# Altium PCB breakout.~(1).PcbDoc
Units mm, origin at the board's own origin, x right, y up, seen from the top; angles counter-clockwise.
Board outline 43.1 x 56.5 mm, 2 copper layers (Top Layer, Bottom Layer); 2 components, 0 nets, 95 pads, 39 vias.
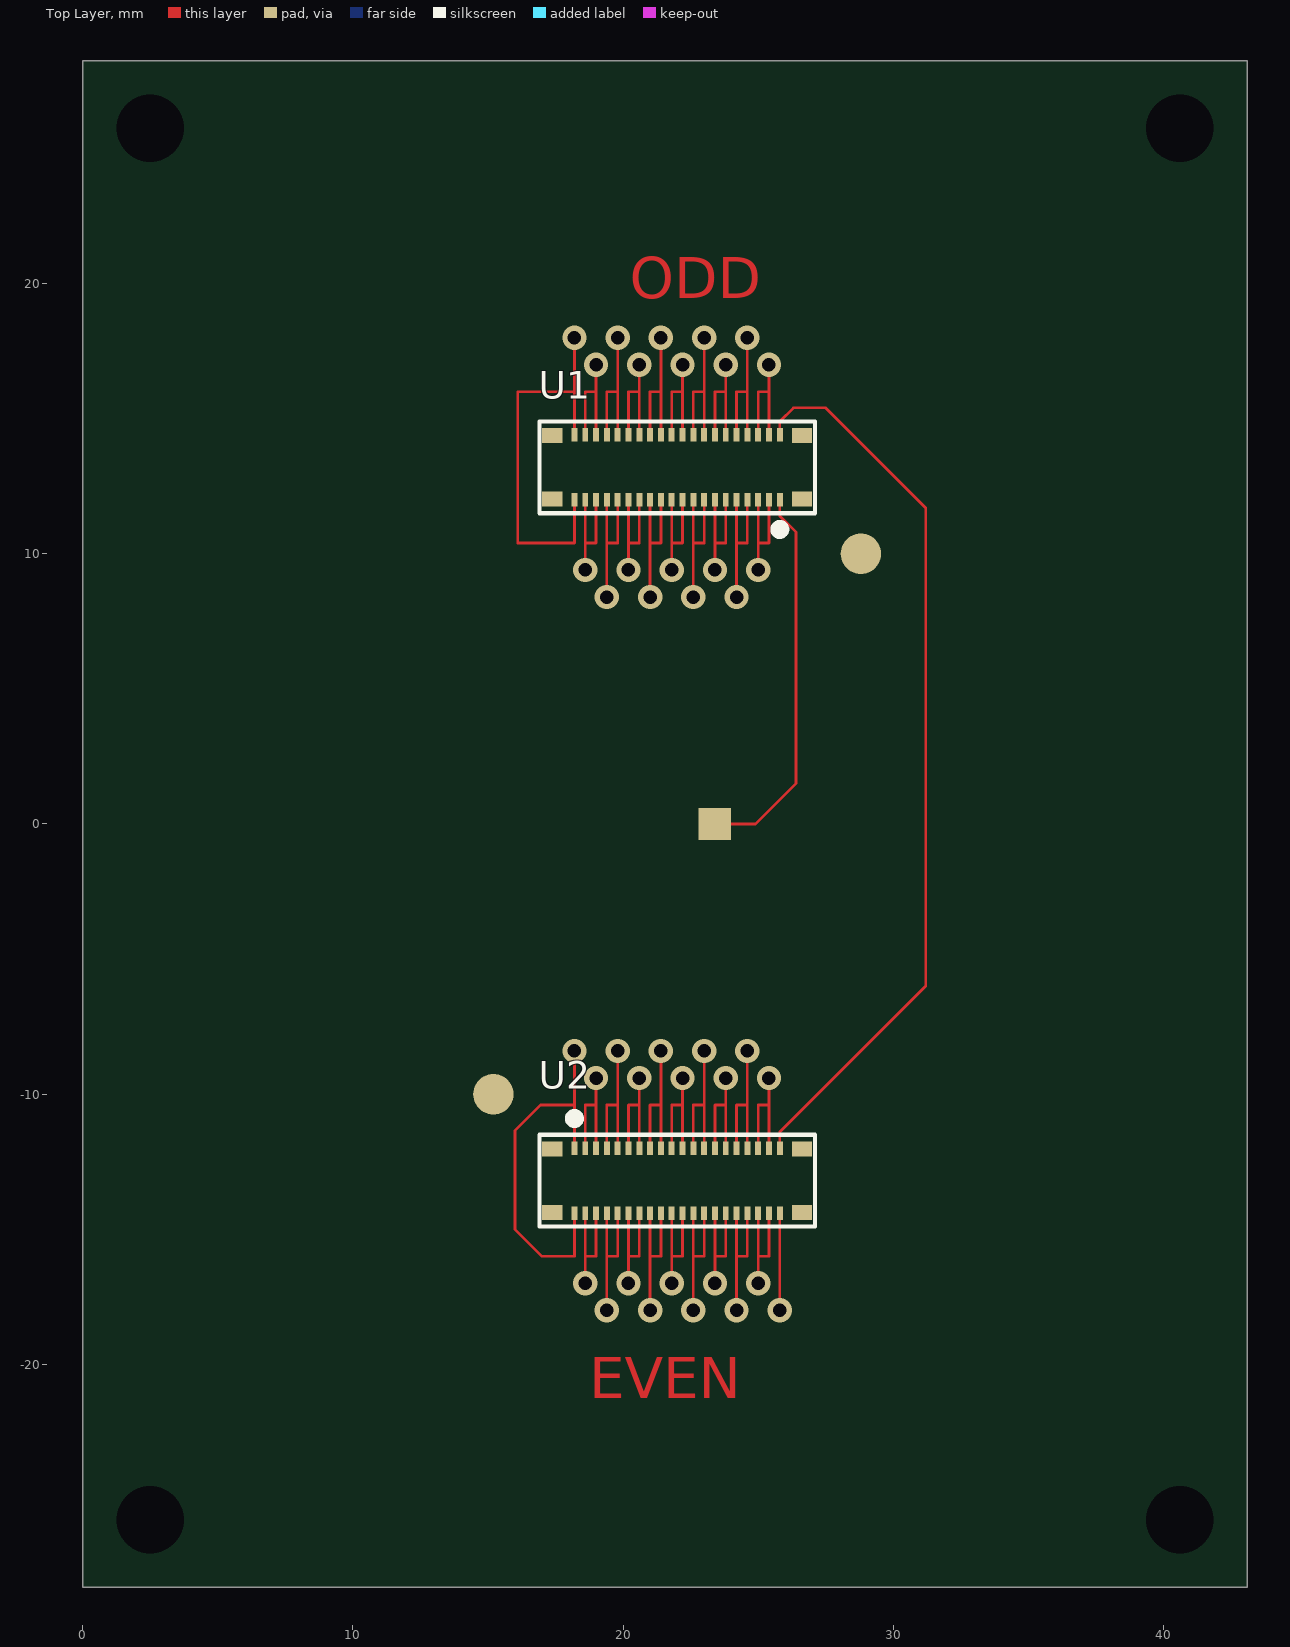
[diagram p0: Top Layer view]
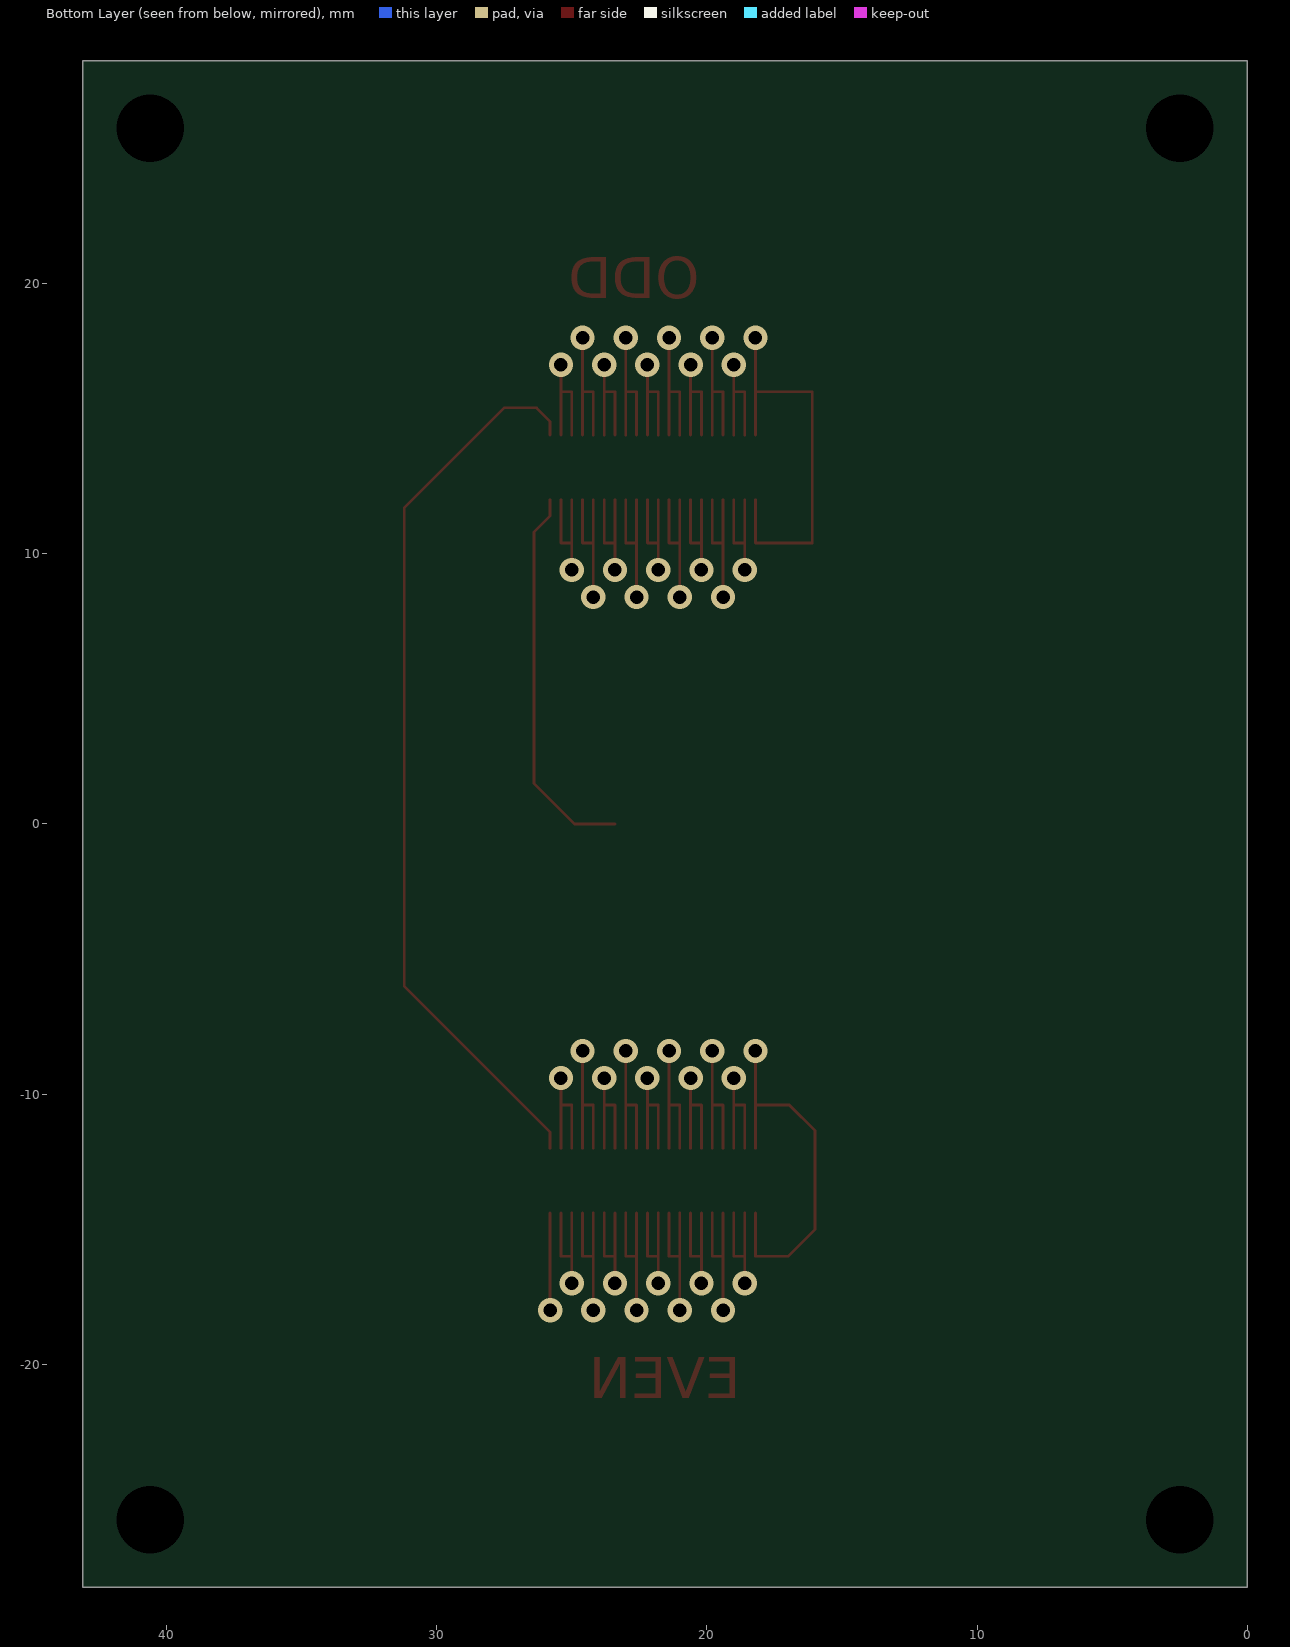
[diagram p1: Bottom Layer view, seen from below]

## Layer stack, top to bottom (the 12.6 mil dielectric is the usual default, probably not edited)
Top Solder: solder mask 0.0102, Solder Resist, Dk 3.5
Top Layer: signal copper 0.0356
Dielectric 1: dielectric 0.32, FR-4, Dk 4.8
Bottom Layer: signal copper 0.0356
Bottom Solder: solder mask 0.0102, Solder Resist, Dk 3.5

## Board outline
0,-28.25 0,28.25 43.1,28.25 43.1,-28.25

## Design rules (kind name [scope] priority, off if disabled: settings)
Clearance [All] p1: gap=0.254 ignorepadtopadclearanceinfootprint=FALSE except(0: Arc-Hole Track-Hole SMDPad-Hole THPad-Hole Via-Hole Fill-Hole Poly-Hole Region-Hole Text-Hole)
PolygonConnect [All] p1: connectstyle=Relief reliefconductorwidth=0.254 reliefentries=4 polygonreliefangle="90 Angle" airgapwidth=0.254
RoutingVias [All] p1: holewidth=0.711 width=1.27 viastyle="Through Hole" minholewidth=0.711 minwidth=1.27 maxholewidth=0.711 maxwidth=1.27
SolderMaskExpansion [All] p1: expansion=0.038 istentingtop=FALSE
Width [All] p1: maxlimit=0.254 minlimit=0.102 preferedwidth=0.254
30 further rules are at their usual default settings.

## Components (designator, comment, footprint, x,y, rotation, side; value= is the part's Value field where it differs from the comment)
U1 "Comment" WP7B-40R 25.8,12 r0 top locked
U2 "Comment" WP7B-40R 18.2,-12 r180 top locked

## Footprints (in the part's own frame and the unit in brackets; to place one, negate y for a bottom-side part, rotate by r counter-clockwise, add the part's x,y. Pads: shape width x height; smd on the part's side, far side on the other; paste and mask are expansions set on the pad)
WP7B-40R [mm]
  rect 0.22x0.5 smd: 1(0,0) 2(-0.4,0) 3(-0.8,0) 4(-1.2,0) 5(-1.6,0) 6(-2,0) 7(-2.4,0) 8(-2.8,0) 9(-3.2,0) 10(-3.6,0) 11(-4,0) 12(-4.4,0) 13(-4.8,0) 14(-5.2,0) 15(-5.6,0) 16(-6,0) 17(-6.4,0) 18(-6.8,0) 19(-7.2,0) 20(-7.6,0) 21(-7.6,2.4) 22(-7.2,2.4) 23(-6.8,2.4) 24(-6.4,2.4) 25(-6,2.4) 26(-5.6,2.4) 27(-5.2,2.4) 28(-4.8,2.4) 29(-4.4,2.4) 30(-4,2.4) 31(-3.6,2.4) 32(-3.2,2.4) 33(-2.8,2.4) 34(-2.4,2.4) 35(-2,2.4) 36(-1.6,2.4) 37(-1.2,2.4) 38(-0.8,2.4) 39(-0.4,2.4) 40(0,2.4)
  rect 0.75x0.55 smd: 41(0.825,0.025) 42(-8.425,0.025) 43(-8.425,2.375) 44(0.825,2.375)
  silkscreen extent -8.9,-1.2 1.3,2.9, body extent -9.1,-0.05 1.5,2.45, height 0.5

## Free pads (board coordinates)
  rect 1.2x1.2 smd paste-2: 0(23.4,0)
  round 1 hole 2.5 unplated: 1(2.5,-25.75) 1(2.5,25.75) 1(40.6,-25.75) 1(40.6,25.75)
  round 1.5 smd paste-2: 1(28.8,10) 4(15.2,-10)

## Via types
v1: diameter 0.9, hole 0.5, Top Layer to Bottom Layer, 39 vias

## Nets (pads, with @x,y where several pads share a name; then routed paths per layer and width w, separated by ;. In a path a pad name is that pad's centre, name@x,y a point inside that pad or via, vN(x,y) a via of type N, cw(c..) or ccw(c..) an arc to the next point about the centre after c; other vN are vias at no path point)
pads on no net: U1.1 U1.2 U1.3 U1.4 U1.5 U1.6 U1.7 U1.8 U1.9 U1.10 U1.11 U1.12 U1.13 U1.14 U1.15 U1.16 U1.17 U1.18 U1.19 U1.20 U1.21 U1.22 U1.23 U1.24 U1.25 U1.26 U1.27 U1.28 U1.29 U1.30 U1.31 U1.32 U1.33 U1.34 U1.35 U1.36 U1.37 U1.38 U1.39 U1.40 U1.41 U1.42 U1.43 U1.44 U2.1 U2.2 U2.3 U2.4 U2.5 U2.6 U2.7 U2.8 U2.9 U2.10 U2.11 U2.12 U2.13 U2.14 U2.15 U2.16 U2.17 U2.18 U2.19 U2.20 U2.21 U2.22 U2.23 U2.24 U2.25 U2.26 U2.27 U2.28 U2.29 U2.30 U2.31 U2.32 U2.33 U2.34 U2.35 U2.36 U2.37 U2.38 U2.39 U2.40 U2.41 U2.42 U2.43 U2.44
copper on no net: | length 262.2
  Top Layer w0.102: 18.2,-14.4 18.2,-16 17,-16 16,-15 16,-11.35 16.95,-10.4 18.2,-10.4 ; 18.2,-12 18.2,-10.4 ; v1(18.2,-8.4) 18.2,-10.4 ; 18.2,12 18.2,10.4 16.1,10.4 16.1,16 18.2,16 ; 18.2,14.4 18.2,16 ; v1(18.2,18) 18.2,16 ; v1(18.6,-17) 18.6,-16 ; 18.6,-14.4 18.6,-16 ; 18.6,-12 18.6,-10.4 19,-10.4 ; v1(18.6,9.4) 18.6,10.4 ; 18.6,12 18.6,10.4 ; 18.6,14.4 18.6,16 19,16 ; 19,-14.4 19,-16 18.6,-16 ; 19,-12 19,-10.4 ; v1(19,-9.4) 19,-10.4 ; 19,12 19,10.4 18.6,10.4 ; 19,14.4 19,16 ; v1(19,17) 19,16 ; v1(19.4,-18) 19.4,-16 ; 19.4,-14.4 19.4,-16 ; 19.4,-12 19.4,-10.4 19.8,-10.4 ; v1(19.4,8.4) 19.4,10.4 ; 19.4,12 19.4,10.4 ; 19.4,14.4 19.4,16 19.8,16 ; 19.8,-14.4 19.8,-16 19.4,-16 ; 19.8,-12 19.8,-10.4 ; v1(19.8,-8.4) 19.8,-10.4 ; 19.8,12 19.8,10.4 19.4,10.4 ; 19.8,14.4 19.8,16 ; v1(19.8,18) 19.8,16 ; v1(20.2,-17) 20.2,-16 ; 20.2,-14.4 20.2,-16 ; 20.2,-12 20.2,-10.4 20.6,-10.4 ; v1(20.2,9.4) 20.2,10.4 ; 20.2,12 20.2,10.4 ; 20.2,14.4 20.2,16 20.6,16 ; 20.6,-14.4 20.6,-16 20.2,-16 ; 20.6,-12 20.6,-10.4 ; v1(20.6,-9.4) 20.6,-10.4 ; 20.6,12 20.6,10.4 20.2,10.4 ; 20.6,14.4 20.6,16 ; v1(20.6,17) 20.6,16 ; v1(21,-18) 21,-16 ; 21,-14.4 21,-16 ; 21,-12 21,-10.4 21.4,-10.4 ; v1(21,8.4) 21,10.4 ; 21,12 21,10.4 ; 21,14.4 21,16 21.4,16 ; 21.4,-14.4 21.4,-16 21,-16 ; 21.4,-12 21.4,-10.4 ; v1(21.4,-8.4) 21.4,-10.4 ; 21.4,12 21.4,10.4 21,10.4 ; 21.4,14.4 21.4,16 ; v1(21.4,18) 21.4,16 ; v1(21.8,-17) 21.8,-16 ; 21.8,-14.4 21.8,-16 ; 21.8,-12 21.8,-10.4 22.2,-10.4 ; v1(21.8,9.4) 21.8,10.4 ; 21.8,12 21.8,10.4 ; 21.8,14.4 21.8,16 22.2,16 ; 22.2,-14.4 22.2,-16 21.8,-16 ; 22.2,-12 22.2,-10.4 ; v1(22.2,-9.4) 22.2,-10.4 ; 22.2,12 22.2,10.4 21.8,10.4 ; 22.2,14.4 22.2,16 ; v1(22.2,17) 22.2,16 ; v1(22.6,-18) 22.6,-16 ; 22.6,-14.4 22.6,-16 ; 22.6,-12 22.6,-10.4 23,-10.4 ; v1(22.6,8.4) 22.6,10.4 ; 22.6,12 22.6,10.4 ; 22.6,14.4 22.6,16 23,16 ; 23,-14.4 23,-16 22.6,-16 ; 23,-12 23,-10.4 ; v1(23,-8.4) 23,-10.4 ; 23,12 23,10.4 22.6,10.4 ; 23,14.4 23,16 ; v1(23,18) 23,16 ; v1(23.4,-17) 23.4,-16 ; 23.4,-14.4 23.4,-16 ; 23.4,-12 23.4,-10.4 23.8,-10.4 ; 23.4,0 24.9,0 26.4,1.5 26.4,10.8 25.8,11.4 25.8,12 ; v1(23.4,9.4) 23.4,10.4 ; 23.4,12 23.4,10.4 ; 23.4,14.4 23.4,16 23.8,16 ; 23.8,-14.4 23.8,-16 23.4,-16 ; 23.8,-12 23.8,-10.4 ; v1(23.8,-9.4) 23.8,-10.4 ; 23.8,12 23.8,10.4 23.4,10.4 ; 23.8,14.4 23.8,16 ; v1(23.8,17) 23.8,16 ; v1(24.2,-18) 24.2,-16 ; 24.2,-14.4 24.2,-16 ; 24.2,-12 24.2,-10.4 24.6,-10.4 ; v1(24.2,8.4) 24.2,10.4 ; 24.2,12 24.2,10.4 ; 24.2,14.4 24.2,16 24.6,16 ; 24.6,-14.4 24.6,-16 24.2,-16 ; 24.6,-12 24.6,-10.4 ; v1(24.6,-8.4) 24.6,-10.4 ; 24.6,12 24.6,10.4 24.2,10.4 ; 24.6,14.4 24.6,16 ; v1(24.6,18) 24.6,16 ; v1(25,-17) 25,-16 ; 25,-14.4 25,-16 ; 25,-12 25,-10.4 25.4,-10.4 ; v1(25,9.4) 25,10.4 ; 25,12 25,10.4 ; 25,14.4 25,16 25.4,16 ; 25.4,-14.4 25.4,-16 25,-16 ; 25.4,-12 25.4,-10.4 ; v1(25.4,-9.4) 25.4,-10.4 ; 25.4,12 25.4,10.4 25,10.4 ; 25.4,14.4 25.4,16 ; v1(25.4,17) 25.4,16 ; v1(25.8,-18) 25.8,-14.4 ; 25.8,-12 25.8,-11.4 31.2,-6 31.2,11.7 27.5,15.4 26.3,15.4 25.8,14.9 25.8,14.4

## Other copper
Top Layer:
  text "ODD" at 20.254,19.454 h1.52
  text "EVEN" at 18.754,-21.246 h1.52

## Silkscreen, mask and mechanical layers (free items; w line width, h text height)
Mechanical 1:
  the board outline again, w0.102

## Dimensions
0,-28.25 to 0,28.25 on Mechanical 14 (Mech14)
0,28.2 to 43.1,28.3 on Mechanical 14 (Mech14)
